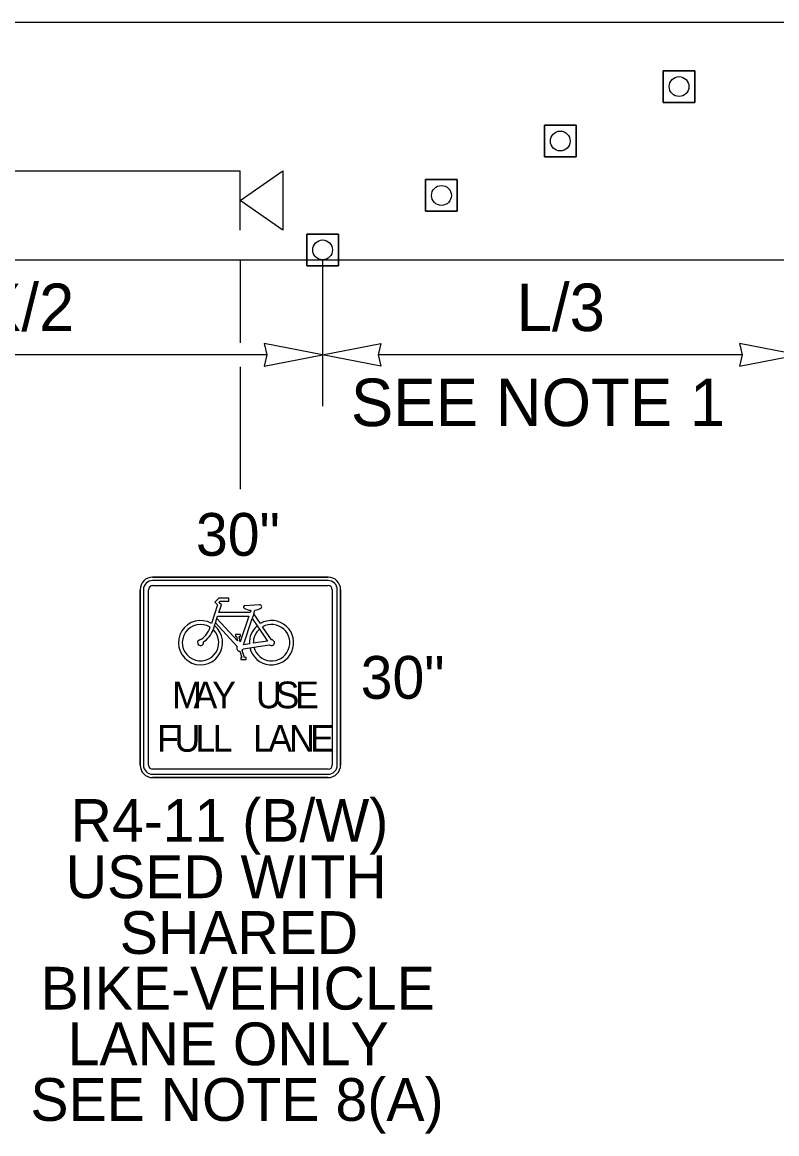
# Model space of a CAD drawing. Extents: x 99999.1 to 100096.1, y 99995 to 100010.7.
# Drawn here: x 100005.543 to 100006.813, y 100003.514 to 100005.386 of the extents above; entities that cross this region are included whole.
import ezdxf

# ---------------------------------------------------------------- set-up
doc = ezdxf.new("R2010")
doc.units = 0
for name, color, linetype in [('RD_ED_ShoulderPavedEdge', 7, 'Continuous'), ('RD_MK_LineEdgeWhite', 7, 'Continuous'), ('TR_SN_ConstructionSigns', 7, 'Continuous'), ('TR_WZ_PortableSignMountBlk-Wht', 7, 'Continuous'), ('TR_WZ_TrafficCone', 7, 'Continuous'), ('TR_WZ_WorkZoneDetails', 7, 'Continuous'), ('TR_WZ_WorkZoneTextCurrent', 7, 'Continuous')]:
    doc.layers.add(name, color=color, linetype=linetype)

msp = doc.modelspace()

# ---------------------------------------------------------------- linework, layer by layer
at = {"layer": 'RD_ED_ShoulderPavedEdge'}
msp.add_line((100000.8283, 100004.9857), (100014.8933, 100004.9857), dxfattribs=at)
at = {"layer": 'RD_MK_LineEdgeWhite'}
msp.add_line((100000.8283, 100005.3857), (100014.8933, 100005.3857), dxfattribs=at)
at = {"layer": 'TR_SN_ConstructionSigns'}
for p, q in [((100005.7625, 100004.4514), (100006.0578, 100004.4514)), ((100006.0578, 100004.4514), (100005.7625, 100004.4514)), ((100006.0578, 100004.4514), (100005.7625, 100004.4514)), ((100006.0578, 100004.4458), (100005.7625, 100004.4458)), ((100005.7414, 100004.135), (100005.7414, 100004.4303)), ((100005.7414, 100004.4303), (100005.7414, 100004.135)), ((100005.7414, 100004.4303), (100005.7414, 100004.135)), ((100005.747, 100004.4303), (100005.747, 100004.135)), ((100005.7554, 100004.135), (100005.7554, 100004.4303)), ((100005.7625, 100004.4374), (100006.0578, 100004.4374)), ((100006.0648, 100004.4303), (100006.0648, 100004.135)), ((100006.0733, 100004.135), (100006.0733, 100004.4303)), ((100006.0789, 100004.4303), (100006.0789, 100004.135)), ((100006.0789, 100004.135), (100006.0789, 100004.4303)), ((100006.0789, 100004.135), (100006.0789, 100004.4303)), ((100005.8741, 100004.4163), (100005.8672, 100004.4093)), ((100005.8672, 100004.4093), (100005.8718, 100004.4047)), ((100005.8906, 100004.4163), (100005.8741, 100004.4163)), ((100005.8742, 100004.4086), (100005.8764, 100004.4108)), ((100005.8782, 100004.4047), (100005.8742, 100004.4086)), ((100005.8764, 100004.4108), (100005.8906, 100004.4108)), ((100005.8906, 100004.4108), (100005.8906, 100004.4163)), ((100005.8718, 100004.4047), (100005.8614, 100004.3735)), ((100005.874, 100004.3922), (100005.8782, 100004.4047)), ((100005.9267, 100004.3922), (100005.874, 100004.3922)), ((100005.9425, 100004.405), (100005.9176, 100004.4034)), ((100005.9278, 100004.3955), (100005.9267, 100004.3922)), ((100005.9328, 100004.3898), (100005.9302, 100004.382)), ((100005.9328, 100004.3898), (100005.9348, 100004.3957)), ((100005.944, 100004.3734), (100005.9328, 100004.3898)), ((100005.8666, 100004.37), (100005.8644, 100004.3632)), ((100005.8666, 100004.37), (100005.8682, 100004.3746)), ((100005.8682, 100004.3746), (100005.8706, 100004.3818)), ((100005.8682, 100004.3746), (100005.9048, 100004.3349)), ((100005.8706, 100004.3818), (100005.8718, 100004.3856)), ((100005.9052, 100004.3441), (100005.8706, 100004.3818)), ((100005.8718, 100004.3856), (100005.9245, 100004.3856)), ((100005.9245, 100004.3856), (100005.91, 100004.3423)), ((100005.9155, 100004.3377), (100005.9302, 100004.382)), ((100005.9302, 100004.382), (100005.9386, 100004.3696)), ((100005.9386, 100004.3696), (100005.9423, 100004.3641)), ((100005.9105, 100004.3549), (100005.9017, 100004.3549)), ((100005.9039, 100004.3516), (100005.9052, 100004.3441)), ((100005.91, 100004.3423), (100005.9083, 100004.3516)), ((100005.9083, 100004.3516), (100005.9105, 100004.3516)), ((100005.9105, 100004.3516), (100005.9105, 100004.3549)), ((100005.9423, 100004.3641), (100005.9561, 100004.3438)), ((100005.9626, 100004.346), (100005.9477, 100004.3679)), ((100005.915, 100004.331), (100005.9263, 100004.3327)), ((100005.9254, 100004.3392), (100005.9155, 100004.3377)), ((100005.9263, 100004.3327), (100005.9328, 100004.3337)), ((100005.9561, 100004.3438), (100005.9319, 100004.3402)), ((100005.9328, 100004.3337), (100005.9591, 100004.3376)), ((100005.9091, 100004.3268), (100005.9127, 100004.316)), ((100005.9127, 100004.316), (100005.9109, 100004.316)), ((100005.9109, 100004.316), (100005.9109, 100004.3127)), ((100005.9109, 100004.3127), (100005.9197, 100004.3127)), ((100005.9174, 100004.316), (100005.9133, 100004.3282)), ((100005.9197, 100004.316), (100005.9174, 100004.316)), ((100005.9197, 100004.3127), (100005.9197, 100004.316)), ((100006.0578, 100004.128), (100005.7625, 100004.128)), ((100005.7625, 100004.1196), (100006.0578, 100004.1196)), ((100006.0578, 100004.1139), (100005.7625, 100004.1139)), ((100005.7625, 100004.1139), (100006.0578, 100004.1139)), ((100005.7625, 100004.1139), (100006.0578, 100004.1139))]:
    msp.add_line(p, q, dxfattribs=at)
msp.add_lwpolyline([(100005.9017, 100004.3549), (100005.9017, 100004.3516), (100005.9039, 100004.3516)], dxfattribs=at)
for centre, radius, start, end in [((100005.7625, 100004.4303), 0.0211, 90, 180), ((100005.7625, 100004.4303), 0.0211, 90, 180), ((100005.7625, 100004.4303), 0.0211, 90, 180), ((100005.7625, 100004.4303), 0.0155, 90, 180), ((100006.0578, 100004.4303), 0.0211, 0, 90), ((100006.0578, 100004.4303), 0.0211, 0, 90), ((100006.0578, 100004.4303), 0.0211, 0, 90), ((100006.0578, 100004.4303), 0.0155, 0, 90), ((100005.7625, 100004.4303), 0.00703, 90, 180), ((100006.0578, 100004.4303), 0.00703, 0, 90), ((100005.9177, 100004.4012), 0.00219, 89.3854, 243.6828), ((100005.9428, 100004.4018), 0.00329, 294.5519, 96.4128), ((100005.8431, 100004.3411), 0.0373, 60.5529, 50.868), ((100005.8431, 100004.3411), 0.0307, 58.1532, 46.1649), ((100005.9626, 100004.3411), 0.0373, 130.0889, 182.8379), ((100005.9626, 100004.3411), 0.0373, 192.9622, 119.9648), ((100005.9626, 100004.3411), 0.0307, 193.937, 119.0598), ((100005.9626, 100004.3411), 0.0307, 131.3616, 181.6359), ((100005.8431, 100004.3411), 0.00493, 105.257, 14.3233), ((100005.9096, 100004.3322), 0.00548, 151.1744, 264.8566), ((100005.9626, 100004.3411), 0.00493, 225.1095, 90.4672), ((100005.9096, 100004.3322), 0.00548, 312.0053, 347.2932), ((100005.7625, 100004.135), 0.0211, 180, 270), ((100005.7625, 100004.135), 0.0211, 180, 270), ((100005.7625, 100004.135), 0.0211, 180, 270), ((100005.7625, 100004.135), 0.0155, 180, 270), ((100005.7625, 100004.135), 0.00703, 180, 270), ((100006.0578, 100004.135), 0.0211, 270, 0), ((100006.0578, 100004.135), 0.0211, 270, 0), ((100006.0578, 100004.135), 0.0155, 270, 0), ((100006.0578, 100004.135), 0.00703, 270, 0), ((100006.0578, 100004.135), 0.0211, 270, 0)]:
    msp.add_arc(centre, radius, start, end, dxfattribs=at)
for centre, major_axis, ratio, start_param, end_param in [((100005.9308, 100004.4064), (-0.0186, 0), 0.588235, 0.686048, 1.410588), ((100005.9308, 100004.4064), (-0.0186, 0), 0.588235, 1.786993, 2.401245), ((100005.848, 100004.3618), (-0.0105, -0.0158), 0.413554, 0.494612, 2.170849), ((100005.848, 100004.3618), (-0.014, -0.021), 0.55814, 0.868091, 1.989998)]:
    msp.add_ellipse(centre, major_axis=major_axis, ratio=ratio, start_param=start_param, end_param=end_param, dxfattribs=at)
at = {"layer": 'TR_WZ_PortableSignMountBlk-Wht'}
msp.add_line((100005.9101, 100005.0358), (100005.9101, 100005.1358), dxfattribs=at)
msp.add_lwpolyline([(100005.9101, 100005.0857), (100005.9819, 100005.1358), (100005.9819, 100005.0358)], close=True, dxfattribs=at)
at = {"layer": 'TR_WZ_TrafficCone'}
for points in [[(100006.622, 100005.3041), (100006.6753, 100005.3041), (100006.6753, 100005.2507), (100006.622, 100005.2507), (100006.622, 100005.3041)], [(100006.622, 100005.2507), (100006.6753, 100005.2507), (100006.6753, 100005.3041), (100006.622, 100005.3041), (100006.622, 100005.2507)], [(100006.422, 100005.2124), (100006.4753, 100005.2124), (100006.4753, 100005.1591), (100006.422, 100005.1591), (100006.422, 100005.2124)], [(100006.422, 100005.1591), (100006.4753, 100005.1591), (100006.4753, 100005.2124), (100006.422, 100005.2124), (100006.422, 100005.1591)], [(100006.222, 100005.1207), (100006.2753, 100005.1207), (100006.2753, 100005.0674), (100006.222, 100005.0674), (100006.222, 100005.1207)], [(100006.222, 100005.0674), (100006.2753, 100005.0674), (100006.2753, 100005.1207), (100006.222, 100005.1207), (100006.222, 100005.0674)], [(100006.0219, 100005.0291), (100006.0753, 100005.0291), (100006.0753, 100004.9757), (100006.0219, 100004.9757), (100006.0219, 100005.0291)], [(100006.0219, 100004.9757), (100006.0753, 100004.9757), (100006.0753, 100005.0291), (100006.0219, 100005.0291), (100006.0219, 100004.9757)]]:
    msp.add_lwpolyline(points, dxfattribs=at)
for centre in [(100006.6487, 100005.2774), (100006.4487, 100005.1857), (100006.2487, 100005.0941), (100006.0486, 100005.0024)]:
    msp.add_circle(centre, 0.0167, dxfattribs=at)
at = {"layer": 'TR_WZ_WorkZoneDetails'}
for p, q in [((100002.4486, 100005.1358), (100005.9101, 100005.1358)), ((100005.9101, 100004.9857), (100005.9101, 100004.8457)), ((100006.0486, 100004.9857), (100006.0486, 100004.7391)), ((100005.9549, 100004.8257), (100005.1423, 100004.8257)), ((100006.7549, 100004.8257), (100006.1423, 100004.8257)), ((100005.9101, 100004.8057), (100005.9101, 100004.5994))]:
    msp.add_line(p, q, dxfattribs=at)
for points in [[(100006.0486, 100004.8257), (100005.9503, 100004.845), (100005.9549, 100004.8257), (100005.9503, 100004.8065)], [(100006.0486, 100004.8257), (100006.1469, 100004.845), (100006.1423, 100004.8257), (100006.1469, 100004.8065)], [(100006.8486, 100004.8257), (100006.7503, 100004.845), (100006.7549, 100004.8257), (100006.7503, 100004.8065)]]:
    msp.add_lwpolyline(points, close=True, dxfattribs=at)

# ---------------------------------------------------------------- texts
at = {"layer": 'TR_SN_ConstructionSigns'}
for s, p in [('30"', (100005.8354, 100004.4874)), ('30"', (100006.1127, 100004.2467)), ('R4-11 (B/W)', (100005.6243, 100004.0059)), ('USED WITH', (100005.6162, 100003.9109)), ('SHARED', (100005.7071, 100003.8171)), ('BIKE-VEHICLE', (100005.574, 100003.7234)), ('LANE ONLY', (100005.6194, 100003.6297)), ('SEE NOTE 8(A)', (100005.5567, 100003.536))]:
    msp.add_text(s, height=0.072, rotation=360, dxfattribs=at).set_placement(p)
for s, p in [('M', (100005.7952, 100004.2307)), ('A', (100005.8312, 100004.2307)), ('Y', (100005.8627, 100004.2307)), ('U', (100005.9365, 100004.2307)), ('S', (100005.9693, 100004.2307)), ('E', (100006.0022, 100004.2307)), ('F', (100005.77, 100004.1575)), ('U', (100005.7992, 100004.1575)), ('L', (100005.8343, 100004.1575)), ('L', (100005.8636, 100004.1575)), ('L', (100005.9315, 100004.1575)), ('A', (100005.9572, 100004.1575)), ('N', (100005.9923, 100004.1575)), ('E', (100006.0274, 100004.1575))]:
    msp.add_text(s, height=0.045, dxfattribs=at).set_placement(p)
at = {"layer": 'TR_WZ_WorkZoneTextCurrent'}
for s, p in [('X/2', (100005.4701, 100004.8657)), ('L/3', (100006.3752, 100004.8657)), ('SEE NOTE 1', (100006.0962, 100004.7057))]:
    msp.add_text(s, height=0.08, rotation=360, dxfattribs=at).set_placement(p)

doc.saveas('drawing.dxf')
